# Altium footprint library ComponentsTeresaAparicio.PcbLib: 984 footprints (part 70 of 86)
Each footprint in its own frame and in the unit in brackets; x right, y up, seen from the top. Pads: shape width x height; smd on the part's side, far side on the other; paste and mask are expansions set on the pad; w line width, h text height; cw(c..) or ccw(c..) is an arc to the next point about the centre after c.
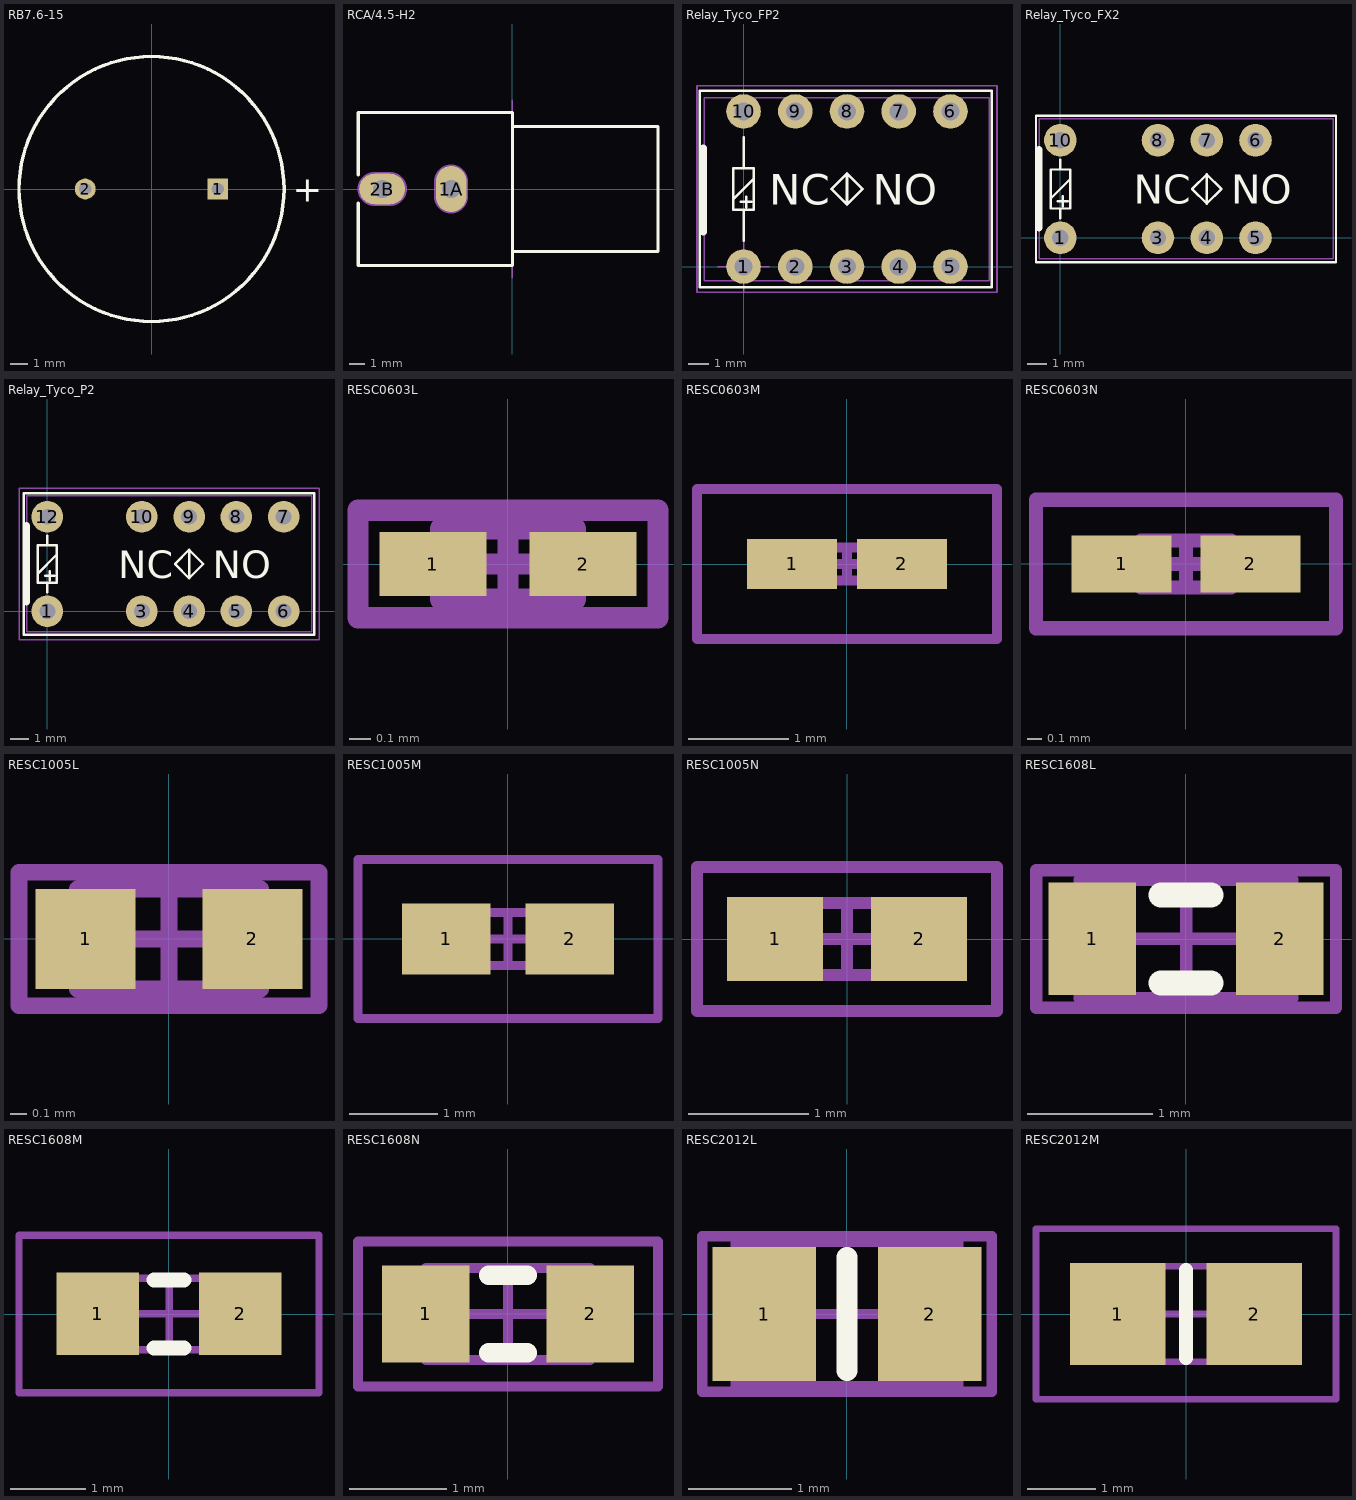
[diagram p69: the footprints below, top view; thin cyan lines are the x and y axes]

## RB7.6-15 [mm] "Polarized Capacitor (Radial); 2 Leads"
pads (2):
  rect 1.2x1.2 hole 0.7: 1(3.81,0)
  round 1.2 hole 0.7: 2(-3.81,0)
Top Overlay:
  circle w0.2: c0,0 r7.62
  text "+" at 8.132,-0.737 h1.5

## RCA/4.5-H2 [mm] "Two Conductor Jack (RCA), Right Angle, Thru-Hole, Body 10 x 10 x 13 mm (WxTxH)"
height 13
pads (2):
  oval 2x3 hole 1.2: 1A(-4,0)
  oval 3x2 hole 1.2: 2B(-8.496,0)
Top Overlay:
  lines w0.2: -10.075,5 -0.018,5 ; -10.057,-0.92 -10.057,-5 0,-5 0,5 ; -10.057,0.92 -10.057,5 ; 0,-4.065 9.5,-4.065 9.5,4.065 0,4.065
Mechanical 1:
  lines w0.1: 0,-5.8 0,5.8
  lines w1.2: -8.996,0 -7.996,0 ; -4,-0.5 -4,0.5
  text "PCB Edge" at -0.333,-4.618 h0.25
  text "Alert PCB fab to slot details" at -10.057,7.842 h0.3
  text "Slot 1.2x2.2mm, PTH" at -10.057,7.342 h0.3
  text "Assign keep-out area to slot" at -10.057,8.342 h0.3
  text "Mech 1 - Slot cut-out" at -10.057,6.842 h0.3
  text "Mech 2 - Clearance, move to internal plane if present" at -10.057,6.342 h0.3
Mechanical 2:
  lines w2.216: -8.996,0 -7.996,0 ; -4,-0.5 -4,0.5

## Relay_Tyco_FP2 [mm] "Tyco FP2 DPDT 5VDC Relay"
height 5.1
pads (10):
  round 1.7 hole 0.889: 1(0,0) 2(2.54,0) 3(5.08,0) 4(7.62,0) 5(10.16,0) 6(10.16,7.62) 7(7.62,7.62) 8(5.08,7.62) 9(2.54,7.62) 10(0,7.62)
Top Overlay:
  lines w0.127: -0.508,3.302 0.508,4.318 ; -0.127,3.175 0.381,3.175 ; 0,1.27 0,2.794 ; 0,4.826 0,6.35 ; 0.127,2.921 0.127,3.429 ; 5.08,3.048 4.318,3.81 5.08,4.572 ; 5.08,3.048 5.08,4.572 ; 5.08,3.048 5.842,3.81 5.08,4.572 ; -2.159,-1.016 -2.159,8.636 12.192,8.636 12.192,-1.016 -2.159,-1.016 ; -0.508,2.794 0.508,2.794 0.508,4.826 -0.508,4.826 -0.508,2.794
  lines w0.381: -1.981,1.727 -1.981,5.817
  text "NC" at 1.27,3.048 h1.5
  text "NO" at 6.35,3.048 h1.5
Mechanical 13:
  lines w0.076: -1.93,-0.7 12.07,-0.7 12.07,8.3 -1.93,8.3 -1.93,-0.7
Mechanical 14:
  lines w0.076: -1.27,0 1.27,0 ; 0,-1.27 0,1.27 ; -2.286,-1.27 12.446,-1.27 12.446,8.89 -2.286,8.89 -2.286,-1.27
3D body: height 5, standoff 0.3, extent -1.93,-0.7 12.07,8.3

## Relay_Tyco_FX2 [mm] "Tyco FX2 DPDT 5VDC Relay"
height 10.7
pads (8):
  round 1.7 hole 0.85: 1(0,0) 3(5.08,0) 4(7.62,0) 5(10.16,0) 6(10.16,5.08) 7(7.62,5.08) 8(5.08,5.08) 10(0,5.08)
Top Overlay:
  lines w0.127: -0.508,2.032 0.508,3.048 ; -0.127,1.905 0.381,1.905 ; 0,1.016 0,1.524 ; 0,3.556 0,4.064 ; 0.127,1.651 0.127,2.159 ; 7.62,1.778 6.858,2.54 7.62,3.302 ; 7.62,1.778 7.62,3.302 ; 7.62,1.778 8.382,2.54 7.62,3.302 ; -1.27,-1.27 -1.27,6.35 14.351,6.35 14.351,-1.27 -1.27,-1.27 ; -0.508,1.524 0.508,1.524 0.508,3.556 -0.508,3.556 -0.508,1.524
  lines w0.381: -1.118,0.508 -1.118,4.597
  text "NC" at 3.81,1.778 h1.5
  text "NO" at 8.89,1.778 h1.5
Mechanical 13:
  lines w0.076: -1.1,-1.1 -1.1,6.2 14.2,6.2 14.2,-1.1 -1.1,-1.1
3D body: height 10.7, standoff 0, extent -1.1,-1.1 14.2,6.2

## Relay_Tyco_P2 [mm] "Tyco P2 DPDT 5VDC V23079 Relay"
height 10
pads (10):
  round 1.7 hole 0.85: 1(0,0) 3(5.08,0) 4(7.62,0) 5(10.16,0) 6(12.7,0) 7(12.7,5.08) 8(10.16,5.08) 9(7.62,5.08) 10(5.08,5.08) 12(0,5.08)
Top Overlay:
  lines w0.127: -0.508,2.032 0.508,3.048 ; -0.127,1.905 0.381,1.905 ; 0,1.016 0,1.524 ; 0,3.556 0,4.064 ; 0.127,1.651 0.127,2.159 ; 7.62,1.778 6.858,2.54 7.62,3.302 ; 7.62,1.778 7.62,3.302 ; 7.62,1.778 8.382,2.54 7.62,3.302 ; -1.27,-1.27 -1.27,6.35 14.351,6.35 14.351,-1.27 -1.27,-1.27 ; -0.508,1.524 0.508,1.524 0.508,3.556 -0.508,3.556 -0.508,1.524
  lines w0.381: -1.118,0.508 -1.118,4.597
  text "NC" at 3.81,1.778 h1.5
  text "NO" at 8.89,1.778 h1.5
Mechanical 13:
  lines w0.076: -1.1,-1.1 -1.1,6.2 14.2,6.2 14.2,-1.1 -1.1,-1.1
Mechanical 14:
  lines w0.076: -0.762,0 0.762,0 ; 0,-0.762 0,0.762 ; -1.524,-1.524 -1.524,6.604 14.6,6.604 14.6,-1.524 -1.524,-1.524
3D body: height 9.82, standoff -0.58, extent -0.9,-1.14 13.6,6.26
3D body: height 10.7, standoff 0, extent -1.1,-1.1 14.2,6.2

## RESC0603L [mm] "Chip Resistor, Body 0.6x0.3mm, IPC High Density"
height 0.3
pads (2):
  rect 0.5x0.3 smd: 1(-0.35,0) 2(0.35,0)
Mechanical 13:
  lines w0.1: -0.315,-0.165 -0.315,0.165 0.315,0.165 0.315,-0.165 -0.315,-0.165
Mechanical 15:
  lines w0.1: -0.165,0 0.165,0 ; 0,-0.165 0,0.165 ; -0.7,-0.25 -0.7,0.25 0.7,0.25 0.7,-0.25 -0.7,-0.25
3D body: height 0.3, standoff 0, extent -0.315,-0.165 0.315,0.165

## RESC0603M [mm] "Chip Resistor, Body 0.6x0.3mm, IPC Low Density"
height 0.3
pads (2):
  rect 0.9x0.5 smd: 1(-0.55,0) 2(0.55,0)
Mechanical 13:
  lines w0.1: -0.315,-0.165 -0.315,0.165 0.315,0.165 0.315,-0.165 -0.315,-0.165
Mechanical 15:
  lines w0.1: -0.165,0 0.165,0 ; 0,-0.165 0,0.165 ; -1.5,-0.75 -1.5,0.75 1.5,0.75 1.5,-0.75 -1.5,-0.75
3D body: height 0.3, standoff 0, extent -0.315,-0.165 0.315,0.165

## RESC0603N [mm] "Chip Resistor, Body 0.6x0.3mm, IPC Medium Density"
height 0.3
pads (2):
  rect 0.7x0.4 smd: 1(-0.45,0) 2(0.45,0)
Mechanical 13:
  lines w0.1: -0.315,-0.165 0.315,-0.165 0.315,0.165 -0.315,0.165 -0.315,-0.165
Mechanical 15:
  lines w0.1: -0.165,0 0.165,0 ; 0,-0.165 0,0.165 ; -1.05,-0.45 1.05,-0.45 1.05,0.45 -1.05,0.45 -1.05,-0.45
3D body: height 0.3, standoff 0, extent -0.315,-0.165 0.315,0.165

## RESC1005L [mm] "Chip Resistor, Body 1.1x0.5mm, IPC High Density"
height 0.4
pads (2):
  rect 0.6x0.6 smd: 1(-0.5,0) 2(0.5,0)
Mechanical 13:
  lines w0.1: -0.55,-0.3 0.55,-0.3 0.55,0.3 -0.55,0.3 -0.55,-0.3
Mechanical 15:
  lines w0.1: -0.3,0 0.3,0 ; 0,-0.3 0,0.3 ; -0.9,-0.4 0.9,-0.4 0.9,0.4 -0.9,0.4 -0.9,-0.4
3D body: height 0.4, standoff 0, extent -0.55,-0.3 0.55,0.3

## RESC1005M [mm] "Chip Resistor, Body 1.1x0.5mm, IPC Low Density"
height 0.4
pads (2):
  rect 1x0.8 smd: 1(-0.7,0) 2(0.7,0)
Mechanical 13:
  lines w0.1: -0.55,-0.3 0.55,-0.3 0.55,0.3 -0.55,0.3 -0.55,-0.3
Mechanical 15:
  lines w0.1: -0.3,0 0.3,0 ; 0,-0.3 0,0.3 ; -1.7,-0.9 1.7,-0.9 1.7,0.9 -1.7,0.9 -1.7,-0.9
3D body: height 0.4, standoff 0, extent -0.55,-0.3 0.55,0.3

## RESC1005N [mm] "Chip Resistor, Body 1.1x0.5mm, IPC Medium Density"
height 0.4
pads (2):
  rect 0.8x0.7 smd: 1(-0.6,0) 2(0.6,0)
Mechanical 13:
  lines w0.1: -0.55,-0.3 -0.55,0.3 0.55,0.3 0.55,-0.3 -0.55,-0.3
Mechanical 15:
  lines w0.1: -0.3,0 0.3,0 ; 0,-0.3 0,0.3 ; -1.25,-0.6 -1.25,0.6 1.25,0.6 1.25,-0.6 -1.25,-0.6
3D body: height 0.4, standoff 0, extent -0.55,-0.3 0.55,0.3

## RESC1608L [mm] "Chip Resistor, Body 1.6x0.8mm, IPC High Density"
height 0.6
pads (2):
  rect 0.7x0.9 smd: 1(-0.75,0) 2(0.75,0)
Top Overlay:
  lines w0.2: -0.2,-0.35 0.2,-0.35 ; -0.2,0.35 0.2,0.35
Mechanical 13:
  lines w0.1: -0.85,-0.475 0.85,-0.475 0.85,0.475 -0.85,0.475 -0.85,-0.475
Mechanical 15:
  lines w0.1: -0.475,0 0.475,0 ; 0,-0.475 0,0.475 ; -1.2,-0.55 1.2,-0.55 1.2,0.55 -1.2,0.55 -1.2,-0.55
3D body: height 0.6, standoff 0, extent -0.85,-0.475 0.85,0.475

## RESC1608M [mm] "Chip Resistor, Body 1.6x0.8mm, IPC Low Density"
height 0.6
pads (2):
  rect 1.1x1.1 smd: 1(-0.95,0) 2(0.95,0)
Top Overlay:
  lines w0.2: -0.2,-0.45 0.2,-0.45 ; -0.2,0.45 0.2,0.45
Mechanical 13:
  lines w0.1: -0.85,-0.475 -0.85,0.475 0.85,0.475 0.85,-0.475 -0.85,-0.475
Mechanical 15:
  lines w0.1: -0.475,0 0.475,0 ; 0,-0.475 0,0.475 ; -2,-1.05 -2,1.05 2,1.05 2,-1.05 -2,-1.05
3D body: height 0.6, standoff 0, extent -0.85,-0.475 0.85,0.475

## RESC1608N [mm] "Chip Resistor, Body 1.6x0.8mm, IPC Medium Density"
height 0.6
pads (2):
  rect 0.9x1 smd: 1(-0.85,0) 2(0.85,0)
Top Overlay:
  lines w0.2: -0.2,-0.4 0.2,-0.4 ; -0.2,0.4 0.2,0.4
Mechanical 13:
  lines w0.1: -0.85,-0.475 0.85,-0.475 0.85,0.475 -0.85,0.475 -0.85,-0.475
Mechanical 15:
  lines w0.1: -0.475,0 0.475,0 ; 0,-0.475 0,0.475 ; -1.55,-0.75 1.55,-0.75 1.55,0.75 -1.55,0.75 -1.55,-0.75
3D body: height 0.6, standoff 0, extent -0.85,-0.475 0.85,0.475

## RESC2012L [mm] "Chip Resistor, Body 2.0x1.3mm, IPC High Density"
height 0.65
pads (2):
  rect 1x1.3 smd: 1(-0.8,0) 2(0.8,0)
Top Overlay:
  lines w0.2: 0,-0.55 0,0.55
Mechanical 13:
  lines w0.1: -1.075,-0.7 -1.075,0.7 1.075,0.7 1.075,-0.7 -1.075,-0.7
Mechanical 15:
  lines w0.1: -0.5,0 0.5,0 ; 0,-0.5 0,0.5 ; -1.4,-0.75 -1.4,0.75 1.4,0.75 1.4,-0.75 -1.4,-0.75
3D body: height 0.65, standoff 0, extent -1.075,-0.7 1.075,0.7

## RESC2012M [mm] "Chip Resistor, Body 2.0x1.3mm, IPC Low Density"
height 0.65
pads (2):
  rect 1.4x1.5 smd: 1(-1,0) 2(1,0)
Top Overlay:
  lines w0.2: 0,-0.65 0,0.65
Mechanical 13:
  lines w0.1: -1.075,-0.7 1.075,-0.7 1.075,0.7 -1.075,0.7 -1.075,-0.7
Mechanical 15:
  lines w0.1: -0.5,0 0.5,0 ; 0,-0.5 0,0.5 ; -2.2,-1.25 2.2,-1.25 2.2,1.25 -2.2,1.25 -2.2,-1.25
3D body: height 0.65, standoff 0, extent -1.075,-0.7 1.075,0.7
